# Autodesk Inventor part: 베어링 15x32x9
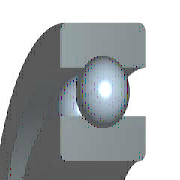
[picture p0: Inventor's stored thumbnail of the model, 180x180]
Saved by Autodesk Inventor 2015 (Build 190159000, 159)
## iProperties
IsCustomPart: 0
Created: 2012-02
Part Number: 베어링 15x32x9
Material: 강철, 연강
Description: 깊은 그루브 볼 베어링
Document SubType Name: Modeling
Standard: KS B 2023
Designer: mduedu
Standards Organization: KS
Language: ko-KR
Size Designation: 6002 - 15 x 32 x 9
Categories: <MemberInstance><Categories><Category DisplayName="샤프트 부품" InternalName="7f7aeb1f-a693-4053-b835-cee3144e0d98" Mnemonic="SHFT"><Category DisplayName="베어링" Inter
Density: 1 g/cm^3
Appearance: 노란색
Author: mduedu
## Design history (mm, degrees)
sketch "스케치" dims "d0" = 4.42 (= -0.26 x WD + 0.26 x BD)
  geometry: L1 (2.29, 11.75)-(6.71, 11.75); L2 (4.5, 11.75)-(4.5, 9.54); L3 (4.5, 11.75)-(4.5, 13.96); L4 (2.858, 10.271)-(0, 10.271); L5 (0, 7.5)-(9, 7.5); L6 (2.858, 13.229)-(0, 13.229); L7 (0, 16)-(9, 16); L8 (9, 7.5)-(9, 10.271); L9 (6.142, 10.271)-(9, 10.271); L10 (6.142, 13.229)-(9, 13.229); L11 (9, 16)-(9, 13.229); L12 (-1.4, 0)-(8.4, 0) reference; L13 (0, -0.3)-(0, 5.3) reference
  constraints: 22 end point, 4 point on line, 2 collinear, 2 perpendicular, 2 symmetric about line, 1 midpoint, 1 parallel, 14 other
  dimensions: "d9" = 15 diameter of L5 L12 (= WD); "d11" = 32 diameter of L7 L12 (= BD); "d12" = 9 distance between parallel lines of L8 L13 (= KB); "d13" = 20.542 diameter of L9 L12 (= 0.326 x BD + 0.674 x WD)
revolve "본체" stored, may be unused: angle "d6" = 90 deg
revolve "볼" stored, may be unused: angle "d7" = 90 deg
pattern_circular "IDS_ARRAYBALL[SIMPL:T]" dims angle "d3" = 360 deg
body "Solid1"
fillet "모깎기1" dims "d1" = 0.3 (= KRS)
other parameters: "WD" = 15 [user parameter; used in 5 equation terms], "BD" = 32 [user parameter; used in 5 equation terms], "KB" = 9 [user parameter; used in 1 equation term], "KRS" = 0.3 [user parameter; used in 1 equation term], "d4" = 0, "d5" = 0, "d8" = 0, "d14" = 0, "d15" = 0, "BBA" = 0 [user parameter], "BC0" = 2850000 [user parameter], "BC" = 5590000 [user parameter], "BR" = 16 (= 0.5 x BD) [user parameter], "WR" = 7.5 (= 0.5 x WD) [user parameter]
